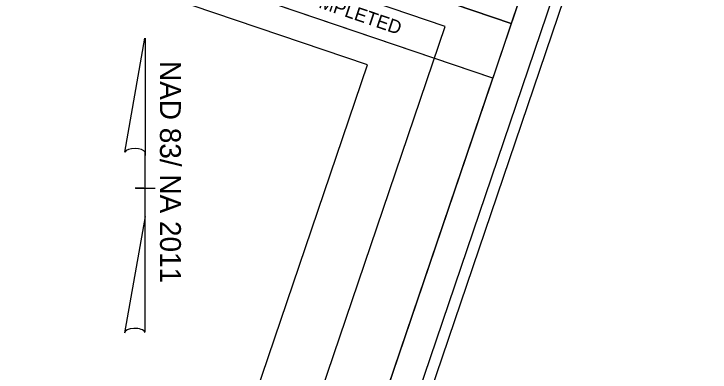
# Model space of a CAD drawing. Extents: x 2298691 to 2299860, y 598939 to 599889.
# Drawn here: x 2299689.8 to 2299859.7, y 599367.9 to 599455.3 of the extents above; entities that cross this region are included whole.
import ezdxf

# ---------------------------------------------------------------- set-up
doc = ezdxf.new("R2010")
doc.units = 0
for name, color, linetype in [('Prop North Arrow NAD83 for Plan Sheets CELL', 7, 'Continuous'), ('Scratch_Level_0', 7, 'Continuous'), ('Sheet Block Title CELL', 7, 'Continuous'), ('Sheet Border Standard 30in CELL', 7, 'Continuous'), ('Sheet Layout Plan Border', 7, 'Continuous'), ('Sheet Plan Layout CELL', 7, 'Continuous'), ('Sheet Plot Border Inside CELL', 7, 'Continuous'), ('Sheet Plot Border Outside CELL', 7, 'Continuous'), ('Sheet Sticker Exception Certification CELL', 7, 'Continuous')]:
    doc.layers.add(name, color=color, linetype=linetype)

msp = doc.modelspace()

# ---------------------------------------------------------------- linework, layer by layer
at = {"layer": 'Prop North Arrow NAD83 for Plan Sheets CELL'}
for p, q in [((2299716.89, 599421.57), (2299721.81, 599449.38)), ((2299721.84, 599449.38), (2299721.84, 599420.7)), ((2299721.84, 599405.82), (2299721.84, 599421.54)), ((2299721.84, 599420.7), (2299721.84, 599421.51)), ((2299719.44, 599412.78), (2299719.41, 599412.78)), ((2299721.57, 599412.78), (2299719.44, 599412.78)), ((2299719.47, 599412.78), (2299724.27, 599412.78)), ((2299721.84, 599405.82), (2299716.83, 599377.47)), ((2299721.87, 599377.59), (2299721.84, 599405.82))]:
    msp.add_line(p, q, dxfattribs=at)
for centre, start_param, end_param in [((2299719.37, 599421.27), 0.216388, 2.908219), ((2299719.37, 599377.37), 0.201328, 3.141593)]:
    msp.add_ellipse(centre, major_axis=(2.54, -0.02), ratio=0.461098, start_param=start_param, end_param=end_param, dxfattribs=at)
at = {"layer": 'Scratch_Level_0'}
msp.add_lwpolyline([(2299002.4, 599823.52), (2298809.46, 599255.41), (2299633.24, 598975.62), (2299795.1, 599452.24), (2299681.46, 599490.84), (2299712.53, 599582.33)], close=True, dxfattribs=at)
at = {"layer": 'Sheet Block Title CELL'}
msp.add_lwpolyline([(2299702.61, 599506.47), (2299816.23, 599467.87), (2299811.17, 599452.96), (2299697.54, 599491.55)], close=True, dxfattribs=at)
at = {"layer": 'Sheet Border Standard 30in CELL'}
msp.add_lwpolyline([(2299845.21, 599553.11), (2298993.02, 599842.55), (2298790.42, 599246.02), (2299642.61, 598956.58)], close=True, dxfattribs=at)
at = {"layer": 'Sheet Layout Plan Border'}
msp.add_lwpolyline([(2299035.49, 599796.46), (2298855.43, 599254), (2299623.37, 598993.18), (2299776.1, 599442.85), (2299690.83, 599471.81), (2299700.48, 599500.22), (2299721.92, 599563.32), (2299035.49, 599796.46)], close=True, dxfattribs=at)
at = {"layer": 'Sheet Plan Layout CELL'}
msp.add_lwpolyline([(2298993.02, 599842.55), (2298790.44, 599246.03), (2299642.62, 598956.59), (2299806.65, 599439.6), (2299693.01, 599478.2), (2299731.56, 599591.71)], close=True, dxfattribs=at)
at = {"layer": 'Sheet Plot Border Inside CELL'}
msp.add_lwpolyline([(2299852.81, 599552.15), (2298906.02, 599873.72), (2298702.43, 599274.29), (2299649.22, 598952.72)], close=True, dxfattribs=at)
at = {"layer": 'Sheet Plot Border Outside CELL'}
msp.add_lwpolyline([(2299859.69, 599564.04), (2298902.97, 599888.98), (2298690.72, 599264.04), (2299647.44, 598939.1)], close=True, dxfattribs=at)
at = {"layer": 'Sheet Sticker Exception Certification CELL'}
for p, q in [((2299697.54, 599491.55), (2299811.19, 599452.95)), ((2299806.65, 599439.6), (2299693.01, 599478.2)), ((2299811.18, 599452.95), (2299806.65, 599439.6))]:
    msp.add_line(p, q, dxfattribs=at)

# ---------------------------------------------------------------- texts
at = {"layer": 'Prop North Arrow NAD83 for Plan Sheets CELL'}
msp.add_text('NAD 83/ NA 2011', height=5.1, rotation=270.0239, dxfattribs=at).set_placement((2299725.47, 599443.79))
at = {"layer": 'Sheet Sticker Exception Certification CELL'}
msp.add_text('UNLESS ALL SIGNATURES COMPLETED', height=3.3, rotation=341.2404, dxfattribs=at).set_placement((2299702.94, 599477.59))

doc.saveas('drawing.dxf')
